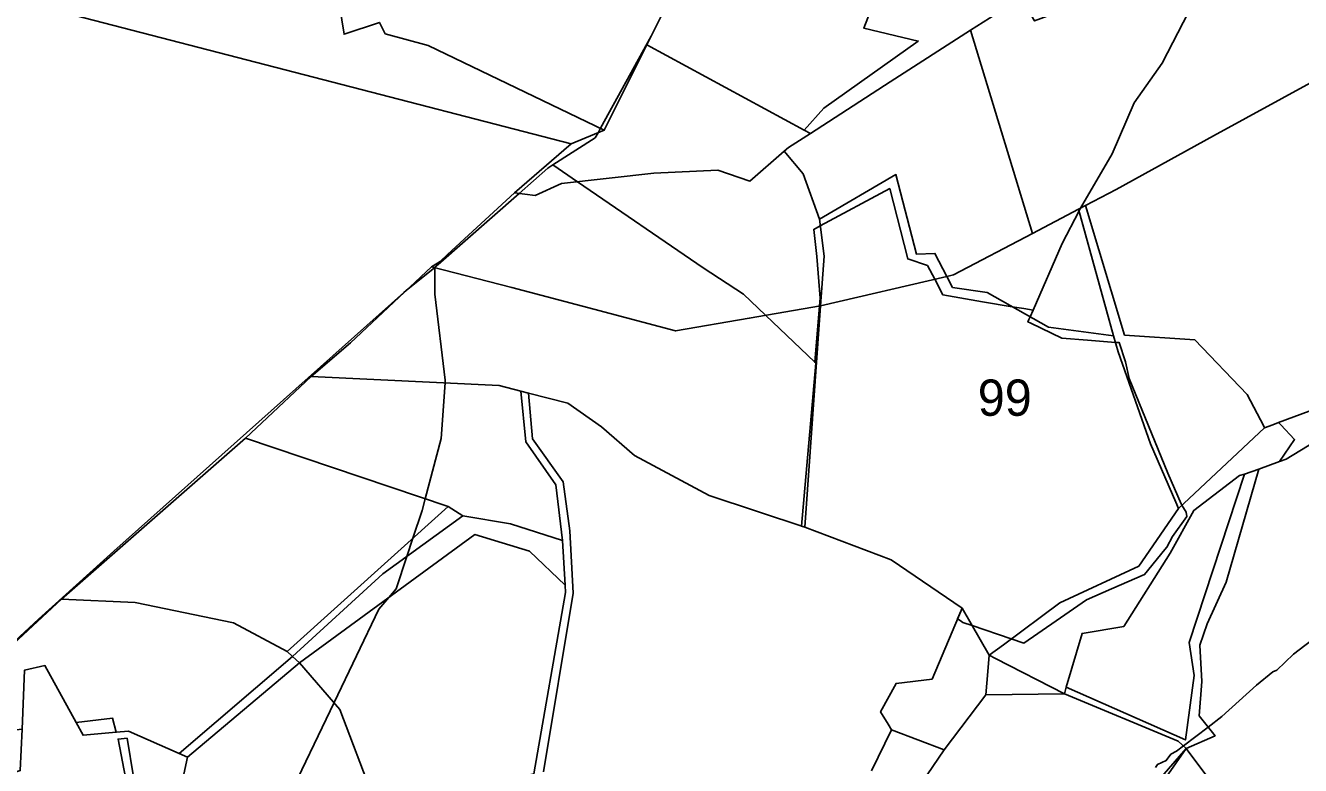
# Model space of a CAD drawing. Extents: x -477304 to -465429, y -1159113 to -1149210.
# Drawn here: x -472912 to -472386, y -1156724 to -1156419 of the extents above; entities that cross this region are included whole.
import ezdxf

# ---------------------------------------------------------------- set-up
doc = ezdxf.new("R2010")
doc.units = 0
for name, color, linetype in [('BPEJ_s', 7, 'Continuous'), ('PUPFL_s', 7, 'Continuous'), ('trav_porost_s', 7, 'Continuous')]:
    doc.layers.add(name, color=color, linetype=linetype)

msp = doc.modelspace()

# ---------------------------------------------------------------- linework, layer by layer
at = {"layer": 'BPEJ_s'}
for points in [[(-472934.11, -1156688.93), (-472906.88, -1156663.82), (-472875.8, -1156635.78), (-472756.02, -1156528.85), (-472755.09, -1156528.09), (-472754.27, -1156527.42), (-472743.42, -1156518.64), (-472743.18, -1156518.45), (-472741.83, -1156517.36), (-472708.42, -1156487.94), (-472696.56, -1156477.49), (-472694.49, -1156476.17), (-472676.96, -1156464.99), (-472675.8, -1156462.88), (-472674.8, -1156461.06), (-472653.86, -1156422.97), (-472648.55, -1156412.31)], [(-472804.84, -1156739.84), (-472784.87, -1156698.32), (-472766.33, -1156659.77), (-472762.28, -1156654.95), (-472759.23, -1156651.32), (-472754.75, -1156637.89), (-472752.27, -1156630.44), (-472748.42, -1156618.89), (-472747.18, -1156614.16), (-472740.65, -1156589.15), (-472739.03, -1156566.22), (-472738.96, -1156565.17), (-472743.18, -1156529.52), (-472743.18, -1156518.7), (-472743.18, -1156518.45), (-472741.83, -1156517.36), (-472708.42, -1156487.94), (-472696.56, -1156477.49), (-472694.49, -1156476.17), (-472684.35, -1156483.11), (-472632.36, -1156518.71), (-472615.81, -1156529.52), (-472606.6, -1156538.31), (-472586.3, -1156557.7), (-472585.91, -1156558.07), (-472591.85, -1156625.35), (-472590.4, -1156625.83), (-472554.72, -1156639.26), (-472525.43, -1156659.31), (-472527.3, -1156663.7), (-472526.28, -1156664.38), (-472525.09, -1156665.17), (-472521.34, -1156666.45), (-472505.12, -1156671.99), (-472500, -1156673.73), (-472486.64, -1156664.49), (-472474.1, -1156655.82), (-472463.76, -1156651.33), (-472450.07, -1156645.39), (-472441.7, -1156635.08), (-472440.92, -1156634.12), (-472438.58, -1156629.66), (-472432.63, -1156621.36), (-472432.84, -1156619.66), (-472434.63, -1156616.8), (-472434.97, -1156616.26), (-472440.5, -1156603.5), (-472456.45, -1156564.36), (-472457.94, -1156557.56), (-472460.55, -1156549.6), (-472462.09, -1156549.48), (-472473.6, -1156548.6), (-472484.31, -1156547.78), (-472497.08, -1156541.6), (-472498.27, -1156541.02), (-472497.84, -1156540.02), (-472497.38, -1156538.96), (-472496.16, -1156536.18), (-472484.1, -1156508.64), (-472477.14, -1156495.14), (-472476.86, -1156494.61), (-472476.7, -1156494.32), (-472476.57, -1156494.09), (-472463.47, -1156471.64), (-472454.32, -1156450.58), (-472442.84, -1156434.21), (-472431.99, -1156413.15)], [(-472431.99, -1156413.15), (-472442.84, -1156434.21), (-472454.32, -1156450.58), (-472463.47, -1156471.64), (-472476.57, -1156494.09), (-472476.7, -1156494.32), (-472476.86, -1156494.61), (-472477.14, -1156495.14), (-472484.1, -1156508.64), (-472496.16, -1156536.18), (-472500, -1156535.55), (-472504.75, -1156534.76), (-472516.99, -1156532.73), (-472533.37, -1156529.86), (-472536.76, -1156523.44), (-472539.79, -1156517.7), (-472547.9, -1156514.99), (-472555.33, -1156485.94), (-472584.02, -1156501.36), (-472586.75, -1156502.83), (-472585.4, -1156513.98), (-472584.05, -1156531.21), (-472584.32, -1156534.41), (-472586.3, -1156557.7), (-472606.6, -1156538.31), (-472615.81, -1156529.52), (-472632.36, -1156518.71), (-472684.35, -1156483.11), (-472694.49, -1156476.17), (-472676.96, -1156464.99), (-472675.8, -1156462.88), (-472674.8, -1156461.06), (-472653.86, -1156422.97), (-472648.55, -1156412.31)], [(-472934.11, -1156688.93), (-472906.88, -1156663.82), (-472875.8, -1156635.78), (-472756.02, -1156528.85), (-472755.09, -1156528.09), (-472754.27, -1156527.42), (-472743.42, -1156518.64), (-472743.18, -1156518.45), (-472743.18, -1156518.7), (-472743.18, -1156529.52), (-472738.96, -1156565.17), (-472739.03, -1156566.22), (-472740.65, -1156589.15), (-472747.18, -1156614.16), (-472748.42, -1156618.89), (-472752.27, -1156630.44), (-472754.75, -1156637.89), (-472759.23, -1156651.32), (-472762.28, -1156654.95), (-472766.33, -1156659.77), (-472784.87, -1156698.32), (-472804.84, -1156739.84)], [(-472445.6, -1156725.15), (-472444.75, -1156723.87), (-472441.14, -1156722.17), (-472439.22, -1156719.62), (-472436.96, -1156718.38), (-472434.05, -1156716.17), (-472423.83, -1156708.4), (-472418.17, -1156704.09), (-472403.92, -1156691.12), (-472397.11, -1156685.59), (-472395.41, -1156684.95), (-472388.6, -1156678.36), (-472378.61, -1156670.7)], [(-472378.61, -1156670.7), (-472388.6, -1156678.36), (-472395.41, -1156684.95), (-472397.11, -1156685.59), (-472403.92, -1156691.12), (-472418.17, -1156704.09), (-472423.83, -1156708.4), (-472434.05, -1156716.17), (-472436.96, -1156718.38), (-472439.22, -1156719.62), (-472441.14, -1156722.17), (-472444.75, -1156723.87), (-472445.6, -1156725.15)]]:
    msp.add_lwpolyline(points, dxfattribs=at)
msp.add_lwpolyline([(-472496.16, -1156536.18), (-472497.38, -1156538.96), (-472497.84, -1156540.02), (-472498.27, -1156541.02), (-472497.08, -1156541.6), (-472484.31, -1156547.78), (-472473.6, -1156548.6), (-472462.09, -1156549.48), (-472460.55, -1156549.6), (-472457.94, -1156557.56), (-472456.45, -1156564.36), (-472440.5, -1156603.5), (-472434.97, -1156616.26), (-472434.63, -1156616.8), (-472432.84, -1156619.66), (-472432.63, -1156621.36), (-472438.58, -1156629.66), (-472440.92, -1156634.12), (-472441.7, -1156635.08), (-472450.07, -1156645.39), (-472463.76, -1156651.33), (-472474.1, -1156655.82), (-472486.64, -1156664.49), (-472500, -1156673.73), (-472505.12, -1156671.99), (-472521.34, -1156666.45), (-472525.09, -1156665.17), (-472526.28, -1156664.38), (-472527.3, -1156663.7), (-472525.43, -1156659.31), (-472554.72, -1156639.26), (-472590.4, -1156625.83), (-472591.85, -1156625.35), (-472585.91, -1156558.07), (-472586.3, -1156557.7), (-472584.32, -1156534.41), (-472584.05, -1156531.21), (-472585.4, -1156513.98), (-472586.75, -1156502.83), (-472584.02, -1156501.36), (-472555.33, -1156485.94), (-472547.9, -1156514.99), (-472539.79, -1156517.7), (-472536.76, -1156523.44), (-472533.37, -1156529.86), (-472516.99, -1156532.73), (-472504.75, -1156534.76), (-472500, -1156535.55)], close=True, dxfattribs=at)
at = {"layer": 'PUPFL_s'}
for points in [[(-472795.42, -1156272.52), (-472806.88, -1156326.38), (-472829.43, -1156340.79), (-472862.8, -1156373.32), (-472856.05, -1156374.79), (-472855.32, -1156391.08), (-472860.9, -1156392.25), (-472857.08, -1156414.67), (-472783.69, -1156403.4), (-472780.72, -1156422.2), (-472766.14, -1156417.35), (-472763.7, -1156422.02), (-472745.95, -1156426.91), (-472673.24, -1156461.81), (-472686.97, -1156467.54), (-472899.78, -1156412.46), (-472863.16, -1156211.61), (-472850.56, -1156204.67), (-472851.22, -1156206.37), (-472862.23, -1156226.24), (-472855.75, -1156241.42), (-472823.38, -1156239.43), (-472797.79, -1156224.95), (-472797.09, -1156241.69)], [(-472766.14, -1156417.35), (-472780.72, -1156422.2), (-472783.69, -1156403.4), (-472784.76, -1156392.72), (-472729.76, -1156381.6), (-472745.94, -1156306.31), (-472745.34, -1156237.48), (-472701.87, -1156251.39), (-472691.02, -1156254.78), (-472703.36, -1156283.5), (-472704.22, -1156311.22), (-472705.41, -1156349.79), (-472706.63, -1156389.44), (-472706.78, -1156397.96), (-472648.55, -1156412.31), (-472655.64, -1156426.53), (-472673.24, -1156461.81), (-472745.95, -1156426.91), (-472763.7, -1156422.02)], [(-472531.75, -1156522.28), (-472536.69, -1156512.73), (-472544.29, -1156513.04), (-472552.76, -1156480.21), (-472584.39, -1156498.6), (-472591.08, -1156479.9), (-472598.95, -1156470.53), (-472597.18, -1156468.98), (-472588.13, -1156463.15), (-472555.15, -1156441.88), (-472522.05, -1156420.47), (-472496.36, -1156504.48), (-472529.01, -1156521.65)], [(-472613.1, -1156482.92), (-472626.39, -1156478.42), (-472652.77, -1156479.6), (-472690.96, -1156483.85), (-472701.75, -1156488.82), (-472710.29, -1156487.69), (-472686.97, -1156467.54), (-472673.24, -1156461.81), (-472655.64, -1156426.53), (-472590.66, -1156461.78), (-472588.13, -1156463.15), (-472597.18, -1156468.98), (-472598.95, -1156470.53)], [(-472677.62, -1156535.75), (-472711.49, -1156526.81), (-472744.55, -1156518.35), (-472740.99, -1156516.02), (-472737.94, -1156513.25), (-472710.29, -1156487.69), (-472701.75, -1156488.82), (-472690.96, -1156483.85), (-472652.77, -1156479.6), (-472626.39, -1156478.42), (-472613.1, -1156482.92), (-472598.95, -1156470.53), (-472591.08, -1156479.9), (-472584.39, -1156498.6), (-472582.37, -1156513.93), (-472583.95, -1156534.35), (-472613.37, -1156539.5), (-472643.82, -1156544.74)], [(-472584.39, -1156498.6), (-472552.76, -1156480.21), (-472544.29, -1156513.04), (-472536.69, -1156512.73), (-472531.75, -1156522.28), (-472583.95, -1156534.35), (-472582.37, -1156513.93)], [(-472437.2, -1156615.54), (-472447.67, -1156591.44), (-472460.93, -1156553.43), (-472462.88, -1156546.83), (-472477.32, -1156494.49), (-472474.53, -1156493.02), (-472458.36, -1156546.45), (-472429.31, -1156548.46), (-472407.68, -1156570.97), (-472400.87, -1156584.16), (-472400.56, -1156584.81), (-472436.06, -1156618.15)], [(-472462.88, -1156546.83), (-472489.81, -1156543.28), (-472515.08, -1156528.87), (-472529.41, -1156526.79), (-472531.75, -1156522.28), (-472529.01, -1156521.65), (-472496.36, -1156504.48), (-472477.32, -1156494.49)], [(-472643.82, -1156544.74), (-472613.37, -1156539.5), (-472583.95, -1156534.35), (-472590.4, -1156625.83), (-472629.98, -1156612.77), (-472660.7, -1156596.17), (-472674.45, -1156584.38), (-472688.27, -1156574.61), (-472704.5, -1156570.43), (-472707.75, -1156569.59), (-472716.62, -1156567.3), (-472794.34, -1156563.57), (-472778.08, -1156549.66), (-472744.55, -1156518.35), (-472711.49, -1156526.81), (-472677.62, -1156535.75)], [(-472436.06, -1156618.15), (-472452.46, -1156641.98), (-472485.02, -1156657.15), (-472508.39, -1156674.4), (-472514.3, -1156678.76), (-472525.43, -1156659.31), (-472554.72, -1156639.26), (-472590.4, -1156625.83), (-472583.95, -1156534.35), (-472531.75, -1156522.28), (-472529.41, -1156526.79), (-472515.08, -1156528.87), (-472489.81, -1156543.28), (-472462.88, -1156546.83), (-472460.93, -1156553.43), (-472447.67, -1156591.44), (-472437.2, -1156615.54)], [(-472705.63, -1156590.57), (-472693.2, -1156608.35), (-472690.44, -1156631.31), (-472712.04, -1156624.41), (-472731.68, -1156621.09), (-472737.72, -1156617.35), (-472821.5, -1156589.09), (-472794.34, -1156563.57), (-472716.62, -1156567.3), (-472707.75, -1156569.59)], [(-472508.39, -1156674.4), (-472485.02, -1156657.15), (-472452.46, -1156641.98), (-472436.06, -1156618.15), (-472400.56, -1156584.81), (-472397.11, -1156583.52), (-472394.76, -1156582.64), (-472393.84, -1156583.61), (-472388.14, -1156589.63), (-472394.29, -1156598.74), (-472402.85, -1156601.83), (-472408.83, -1156604), (-472410.88, -1156604.47), (-472429.76, -1156618.89), (-472439.49, -1156636.61), (-472458.68, -1156666.86), (-472475.87, -1156669.7), (-472482.41, -1156691.96), (-472483.21, -1156694.68), (-472511.7, -1156680.09), (-472514.3, -1156678.76)], [(-472897.38, -1156655.6), (-472821.5, -1156589.09), (-472737.72, -1156617.35), (-472804.22, -1156677.17), (-472826.39, -1156665.35), (-472866.96, -1156656.98)], [(-472532.82, -1156717.86), (-472554.55, -1156709.55), (-472555.97, -1156707.24), (-472559.13, -1156702.14), (-472552.69, -1156690.37), (-472537.88, -1156688.58), (-472525.43, -1156659.31), (-472514.3, -1156678.76), (-472514.85, -1156685.5), (-472515.63, -1156695.03)], [(-472483.21, -1156694.68), (-472515.63, -1156695.03), (-472514.85, -1156685.5), (-472514.3, -1156678.76), (-472511.7, -1156680.09)]]:
    msp.add_lwpolyline(points, close=True, dxfattribs=at)
msp.add_lwpolyline([(-472899.78, -1156412.46), (-472686.97, -1156467.54), (-472710.29, -1156487.69), (-472737.94, -1156513.25), (-472740.99, -1156516.02), (-472744.55, -1156518.35), (-472778.08, -1156549.66), (-472794.34, -1156563.57), (-472821.5, -1156589.09), (-472897.38, -1156655.6), (-472938.95, -1156694.18), (-472946.03, -1156689.3), (-472958.61, -1156680.63), (-473010.93, -1156644.58), (-473083.16, -1156591.9), (-473126.32, -1156560.34), (-473104.01, -1156496.44), (-473108.89, -1156463.38), (-473100.49, -1156468.81), (-473078.33, -1156321.91)], dxfattribs=at)
at = {"layer": 'trav_porost_s'}
for points in [[(-472561.78, -1156408.65), (-472566.11, -1156419.68), (-472543.56, -1156425.03), (-472582.58, -1156452.7), (-472590.66, -1156461.78), (-472655.64, -1156426.53), (-472648.55, -1156412.31), (-472643.11, -1156403.47), (-472631.43, -1156384.65), (-472629.13, -1156385.75), (-472611.4, -1156359.69), (-472565.25, -1156380.57), (-472534.6, -1156386.16), (-472533.46, -1156383.61), (-472513.64, -1156389.2), (-472510.04, -1156390.25), (-472513.7, -1156396.98), (-472518.39, -1156406.05), (-472547.68, -1156399.33), (-472550.59, -1156403.35), (-472554.29, -1156403.53), (-472554.94, -1156410.64)], [(-472367.51, -1156434.56), (-472380, -1156441.42), (-472421.57, -1156464.24), (-472461.88, -1156486.38), (-472474.53, -1156493.02), (-472477.32, -1156494.49), (-472496.36, -1156504.48), (-472522.05, -1156420.47), (-472501.07, -1156407.1), (-472495.6, -1156416.72), (-472389.31, -1156377.26)], [(-472554.94, -1156410.64), (-472554.29, -1156403.53), (-472550.59, -1156403.35), (-472547.68, -1156399.33), (-472518.39, -1156406.05), (-472513.7, -1156396.98), (-472501.07, -1156407.1), (-472522.05, -1156420.47), (-472555.15, -1156441.88), (-472588.13, -1156463.15), (-472590.66, -1156461.78), (-472582.58, -1156452.7), (-472543.56, -1156425.03), (-472566.11, -1156419.68), (-472561.78, -1156408.65)], [(-472293.07, -1156526.4), (-472291.38, -1156529.79), (-472303.23, -1156554.32), (-472309.34, -1156558.68), (-472313.25, -1156561.47), (-472320.55, -1156566.67), (-472320.83, -1156566.61), (-472340.42, -1156562.34), (-472351.41, -1156566.44), (-472382.15, -1156577.93), (-472394.76, -1156582.64), (-472397.11, -1156583.52), (-472400.56, -1156584.81), (-472400.87, -1156584.16), (-472407.68, -1156570.97), (-472429.31, -1156548.46), (-472458.36, -1156546.45), (-472474.53, -1156493.02), (-472461.88, -1156486.38), (-472421.57, -1156464.24), (-472380, -1156441.42), (-472367.51, -1156434.56), (-472344.91, -1156422.16)], [(-472416.34, -1156648.59), (-472424.28, -1156665.71), (-472427.29, -1156674.6), (-472426.47, -1156689.61), (-472427.52, -1156703.76), (-472420.96, -1156712.01), (-472432.86, -1156717.23), (-472436.15, -1156714.29), (-472483.21, -1156694.68), (-472482.41, -1156691.96), (-472433.2, -1156713.71), (-472429.61, -1156687.16), (-472431.62, -1156673.53), (-472408.83, -1156604), (-472402.85, -1156601.83)], [(-472429.76, -1156618.89), (-472410.88, -1156604.47), (-472408.83, -1156604), (-472431.62, -1156673.53), (-472429.61, -1156687.16), (-472433.2, -1156713.71), (-472482.41, -1156691.96), (-472475.87, -1156669.7), (-472458.68, -1156666.86), (-472439.49, -1156636.61)], [(-472801.98, -1156679.26), (-472764.65, -1156645.09), (-472731.68, -1156621.09), (-472712.04, -1156624.41), (-472690.44, -1156631.31), (-472689.39, -1156649.79), (-472704.18, -1156635.8), (-472726.68, -1156628.91), (-472799.15, -1156681.92)], [(-472689.23, -1156652.78), (-472702.29, -1156727.7), (-472756.56, -1156740.03), (-472768.63, -1156737.77), (-472782.43, -1156701.13), (-472799.15, -1156681.92), (-472726.68, -1156628.91), (-472704.18, -1156635.8), (-472689.39, -1156649.79)], [(-472938.47, -1156712.18), (-472943.55, -1156712.79), (-472946.03, -1156689.3), (-472938.95, -1156694.18), (-472897.38, -1156655.6), (-472866.96, -1156656.98), (-472826.39, -1156665.35), (-472804.22, -1156677.17), (-472801.98, -1156679.26), (-472848.79, -1156719.38), (-472869.82, -1156710.1), (-472874.83, -1156710.56), (-472876.41, -1156704.73), (-472891.43, -1156706.53), (-472904.28, -1156683.04), (-472912.66, -1156684.85), (-472913.72, -1156709.21)], [(-472845.41, -1156720.87), (-472851.56, -1156749.67), (-472875.57, -1156741.37), (-472867.66, -1156728.95), (-472870.37, -1156713.03), (-472874.06, -1156713.38), (-472871.03, -1156729.26), (-472887.62, -1156749.47), (-472936.69, -1156737.51), (-472943.93, -1156733.17), (-472937.06, -1156732.32), (-472930.84, -1156731.55), (-472914.47, -1156726.41), (-472913.72, -1156709.21), (-472912.66, -1156684.85), (-472904.28, -1156683.04), (-472891.43, -1156706.53), (-472888.54, -1156711.81), (-472874.83, -1156710.56), (-472869.82, -1156710.1), (-472848.79, -1156719.38)], [(-472845.41, -1156720.87), (-472799.15, -1156681.92), (-472782.43, -1156701.13), (-472768.63, -1156737.77), (-472774.46, -1156736.54), (-472807.16, -1156750.98), (-472810.62, -1156745.76), (-472827.55, -1156749.32), (-472836.92, -1156742.16), (-472846.65, -1156751.28), (-472851.56, -1156749.67)], [(-472801.98, -1156679.26), (-472799.15, -1156681.92), (-472845.41, -1156720.87), (-472848.79, -1156719.38)], [(-472479.61, -1156811), (-472502.12, -1156799.6), (-472518.57, -1156794.35), (-472523.6, -1156796.04), (-472527.1, -1156793.63), (-472566.14, -1156766.88), (-472532.82, -1156717.86), (-472515.63, -1156695.03), (-472483.21, -1156694.68), (-472436.15, -1156714.29), (-472432.86, -1156717.23), (-472444.69, -1156730.83), (-472452.68, -1156743.3), (-472457.18, -1156761.73), (-472458.62, -1156773.31), (-472462.3, -1156778.28), (-472459.86, -1156780.26), (-472466.92, -1156795.2)], [(-472888.54, -1156711.81), (-472891.43, -1156706.53), (-472876.41, -1156704.73), (-472874.83, -1156710.56)], [(-472453.96, -1156756.86), (-472445.34, -1156735.08), (-472432.86, -1156717.23), (-472395.47, -1156767.24), (-472391.29, -1156773.52), (-472426.01, -1156787.57), (-472428.06, -1156799.22), (-472436.92, -1156805.09), (-472454.41, -1156780.18)]]:
    msp.add_lwpolyline(points, close=True, dxfattribs=at)
for points in [[(-472698.38, -1156726.95), (-472686.14, -1156653.06), (-472687.41, -1156627.3), (-472690.22, -1156607.07), (-472702.84, -1156589.34), (-472704.5, -1156570.43), (-472688.27, -1156574.61), (-472674.45, -1156584.38), (-472660.7, -1156596.17), (-472629.98, -1156612.77), (-472590.4, -1156625.83), (-472554.72, -1156639.26), (-472525.43, -1156659.31), (-472537.88, -1156688.58), (-472552.69, -1156690.37), (-472559.13, -1156702.14), (-472555.97, -1156707.24), (-472554.55, -1156709.55), (-472562.87, -1156726.46)], [(-472366.12, -1156746.03), (-472395.47, -1156767.24), (-472432.86, -1156717.23), (-472420.96, -1156712.01), (-472427.52, -1156703.76), (-472426.47, -1156689.61), (-472427.29, -1156674.6), (-472424.28, -1156665.71), (-472416.34, -1156648.59), (-472402.85, -1156601.83), (-472394.29, -1156598.74), (-472391.67, -1156597.79), (-472373.99, -1156587.03)], [(-472444.69, -1156730.83), (-472432.86, -1156717.23), (-472445.34, -1156735.08)]]:
    msp.add_lwpolyline(points, dxfattribs=at)

# ---------------------------------------------------------------- texts
at = {"layer": 'BPEJ_s'}
msp.add_text('99', height=15, dxfattribs=at).set_placement((-472518.99, -1156579.83))

doc.saveas('drawing.dxf')
